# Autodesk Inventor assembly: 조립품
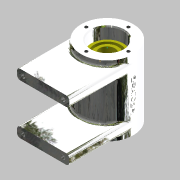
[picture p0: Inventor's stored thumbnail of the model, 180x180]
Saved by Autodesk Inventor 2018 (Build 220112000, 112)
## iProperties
Created: 2020-07
Part Number: 조립품
Material: 일반
Document SubType Name: Assembly
Designer: home
Author: home
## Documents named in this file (3)
- C:\Users\home\Desktop\700706V1026\조립품.iam
- C:\Users\home\Desktop\700706V1026\본체.ipt
- C:\Users\home\Desktop\700706V1026\베어링 6002.ipt
